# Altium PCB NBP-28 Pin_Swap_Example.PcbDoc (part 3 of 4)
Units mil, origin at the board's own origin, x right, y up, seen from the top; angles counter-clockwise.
Board outline 2716.54 x 4967.15 mil, 10 copper layers (Top Layer, Mid-Layer 1, VCC1V2, Mid-Layer 2, VCC, GND, MidLayer4, VCCINT, Mid-Layer 3, Bottom Layer), stack 81 mil thick; 254 components, 445 nets, 1667 pads, 770 vias.
Unrouted connection lines stored in the file: 611.
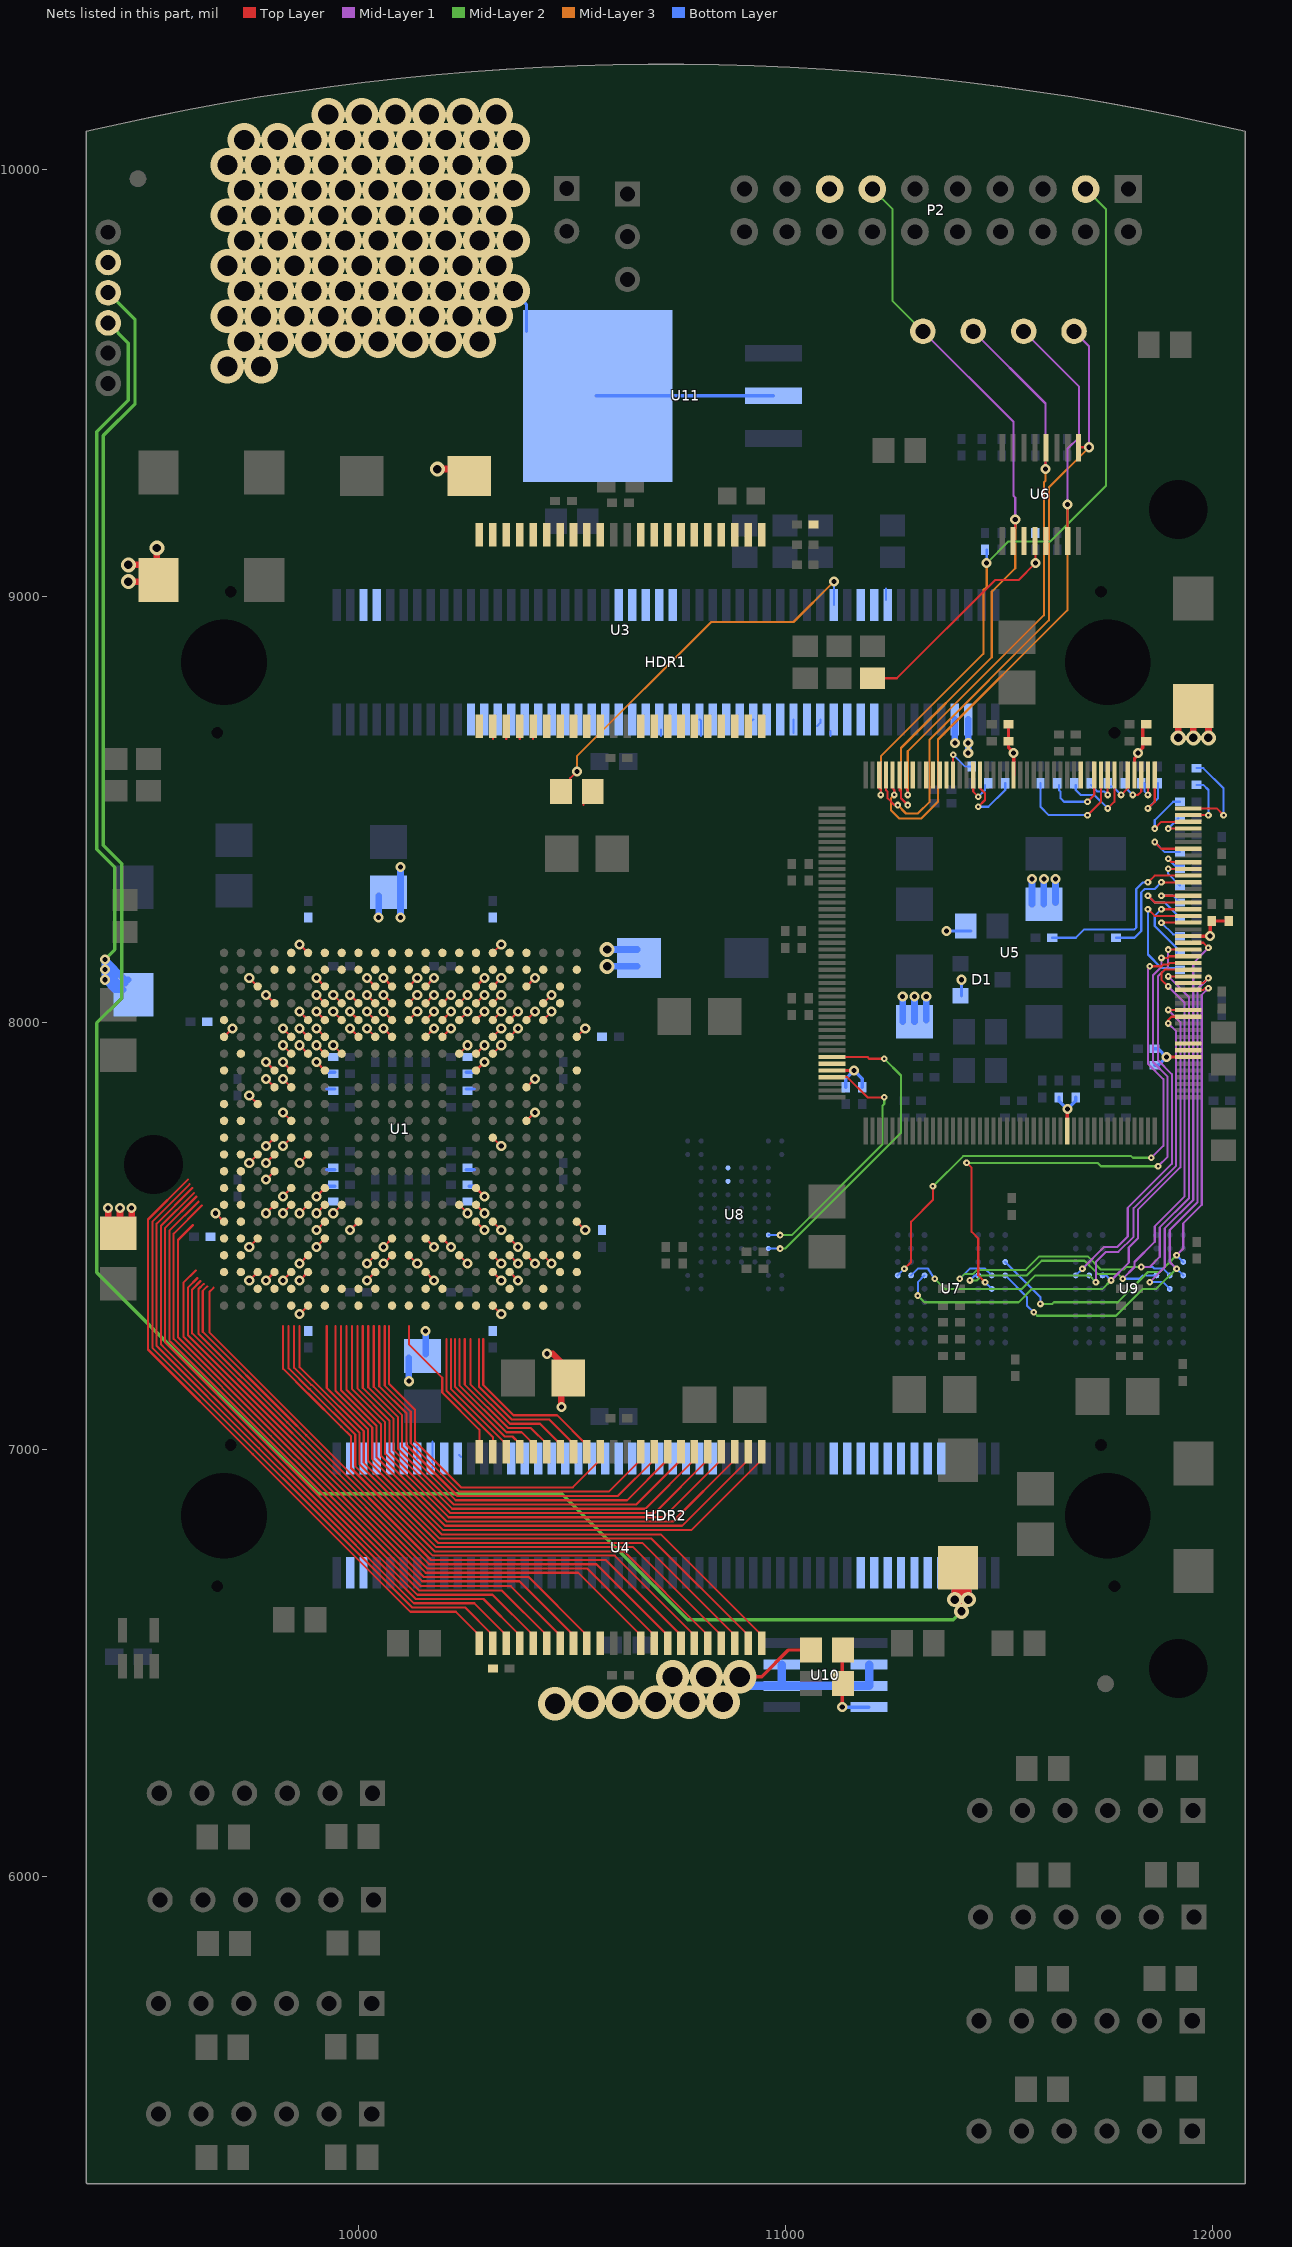
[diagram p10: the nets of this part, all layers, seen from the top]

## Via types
v1: diameter 23.62, hole 11.81, Top Layer to Bottom Layer, 495 vias
v2: diameter 78.74, hole 47.24, Top Layer to Bottom Layer, 101 vias
v3: diameter 15.75, hole 5.91, Top Layer to Bottom Layer, 92 vias
v4: diameter 35.43, hole 19.68, Top Layer to Bottom Layer, 59 vias
v5: diameter 19.68, hole 7.87, Top Layer to Bottom Layer, 23 vias

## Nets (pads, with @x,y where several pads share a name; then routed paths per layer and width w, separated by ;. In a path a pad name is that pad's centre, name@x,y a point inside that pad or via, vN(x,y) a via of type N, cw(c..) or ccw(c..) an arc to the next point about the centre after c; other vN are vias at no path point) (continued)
NetR26_1: R26.1 U5.126 | length 154.1
  Top Layer w5: v3(11865.62,8424.19) 11881.37,8408.44 U5.126@11944.36,8408.44
  Bottom Layer w5: v3(11865.62,8424.19) 11889.24,8400.57 R26.1@11924.67,8400.57
NetR27_1: R27.1 U5.124 | length 92.5
  Top Layer w5: v3(11897.11,8384.82) 11904.99,8376.95 U5.124@11944.36,8376.95
  Bottom Layer w5: v3(11897.11,8384.82) 11912.86,8369.07 R27.1@11932.55,8369.07
NetR28_1: R28.1 U5.123 | length 98
  Top Layer w5: v3(11897.11,8361.2) U5.123@11944.36,8361.2
  Bottom Layer w5: v3(11897.11,8361.2) 11897.11,8349.39 R28.1@11924.67,8321.83
NetR29_1: R29.1 U5.122 | length 432.3
  Top Layer w5: v3(11849.87,8329.7) 11865.62,8345.45 U5.122@11944.36,8345.45
  Bottom Layer w5: R29.1@11625.46,8199.78 11680.58,8199.78 11700.26,8219.47 11818.37,8219.47 11822.31,8223.41 11822.31,8313.96 11838.06,8329.7 v3(11849.87,8329.7)
NetR30_1: R30.1 U5.121 | length 276.1
  Top Layer w5: v3(11881.37,8329.7) U5.121@11944.36,8329.7
  Bottom Layer w5: R30.1@11775.07,8199.78 11818.37,8199.78 11834.12,8215.53 11834.12,8306.08 11842,8313.96 11865.62,8313.96 v3(11881.37,8329.7)
NetR31_1: R31.1 U5.119 | length 112.8
  Top Layer w5: v3(11881.37,8298.21) U5.119@11944.36,8298.21
  Bottom Layer w5: v3(11881.37,8298.21) 11908.93,8298.21 R31.1@11924.67,8282.46
NetR32_1: R32.1 U5.118 | length 197.7
  Top Layer w5: v3(11849.87,8298.21) 11865.62,8282.46 U5.118@11944.36,8282.46
  Bottom Layer w5: v3(11849.87,8298.21) 11865.62,8282.46 11889.24,8282.46 11916.8,8254.9 R32.1@11916.8,8243.09
NetR33_1: R33.1 U5.117 | length 193.1
  Top Layer w5: v3(11881.37,8266.71) U5.117@11944.36,8266.71
  Bottom Layer w5: v3(11881.37,8266.71) 11865.62,8250.96 11865.62,8227.34 11916.8,8176.16 R33.1@11916.8,8164.35
NetR34_1: R34.1 U5.116 | length 299.1
  Top Layer w5: v3(11849.87,8266.71) 11865.62,8250.96 U5.116@11944.36,8250.96
  Bottom Layer w5: v3(11849.87,8266.71) 11849.87,8160.41 11881.37,8128.92 R34.1@11928.61,8128.92
NetR35_1: R35.1 U5.115 | length 125.6
  Top Layer w5: v3(11881.37,8235.22) U5.115@11944.36,8235.22
  Bottom Layer w5: v3(11881.37,8235.22) 11908.93,8207.66 R35.1@11932.55,8207.66
NetR39_1: R39.1 U5.129 | length 80.6
  Top Layer w5: v3(11897.11,8455.69) U5.129@11944.36,8455.69
  Bottom Layer w5: v3(11897.11,8455.69) R39.1@11920.74,8479.31
NetR40_1: R40.1 U5.131 | length 138.8
  Top Layer w5: U5.131@11944.36,8487.18 v3(11991.6,8487.18)
  Bottom Layer w5: R40.1@11964.04,8558.05 11979.79,8558.05 11991.6,8546.24 v3(11991.6,8487.18)
NetR41_1: R41.1 U5.133 | length 154.1
  Top Layer w5: v3(11849.87,8502.93) 11865.62,8518.68 U5.133@11865.62,8581.67
  Bottom Layer w5: v3(11849.87,8502.93) 11873.49,8526.56 R41.1@11873.49,8561.99
NetR42_1: R42.1 U5.134 | length 78.1
  Top Layer w5: v3(11849.87,8534.43) U5.134@11849.87,8581.67
  Bottom Layer w5: R42.1@11842,8561.99 11842,8542.3 v3(11849.87,8534.43)
NetR43_1: R43.1 U5.135 | length 98.7
  Top Layer w5: v3(11814.44,8534.43) 11826.25,8534.43 11834.12,8542.3 U5.135@11834.12,8581.67
  Bottom Layer w5: R43.1@11802.63,8565.92 11802.63,8546.24 v3(11814.44,8534.43)
NetR45_1: R45.1 U5.137 | length 93.4
  Top Layer w5: v3(11786.88,8534.43) 11802.63,8550.18 U5.137@11802.63,8581.67
  Bottom Layer w5: R45.1@11755.38,8554.11 11767.19,8554.11 v3(11786.88,8534.43)
NetR48_1: R48.1 U5.130 | length 181.9
  Top Layer w5: v3(11865.62,8455.69) 11881.37,8471.44 U5.130@11944.36,8471.44
  Bottom Layer w5: v3(11865.62,8455.69) 11865.62,8475.37 11908.93,8518.68 R48.1@11924.67,8518.68
NetR49_1: R49.1 U5.132 | length 234.8
  Top Layer w5: U5.132@11944.36,8502.93 12011.29,8502.93 v3(12027.04,8487.18)
  Bottom Layer w5: R49.1@11964.04,8597.42 11979.79,8597.42 12027.04,8550.18 v3(12027.04,8487.18)
NetR50_1: R50.1 U5.139 | length 189.8
  Top Layer w5: v3(11755.38,8502.93) 11771.13,8518.68 U5.139@11771.13,8581.67
  Bottom Layer w5: R50.1@11680.58,8558.05 11680.58,8546.24 11692.39,8534.43 11723.89,8534.43 v3(11755.38,8502.93)
NetR51_1: R51.1 U5.140 | length 96.4
  Top Layer w5: v3(11755.38,8534.43) U5.140@11755.38,8581.67
  Bottom Layer w5: R51.1@11716.01,8558.05 11731.39,8542.68 11747.13,8542.68 v3(11755.38,8534.43)
NetR52_1: R52.1 U5.141 | length 281
  Top Layer w5: v3(11708.14,8487.18) 11739.63,8518.68 U5.141@11739.63,8581.67
  Bottom Layer w5: R52.1@11597.9,8561.99 11597.9,8506.87 11617.59,8487.18 v3(11708.14,8487.18)
NetR53_1: R53.1 U5.142 | length 168.9
  Top Layer w5: v3(11708.14,8518.68) 11723.89,8534.43 U5.142@11723.89,8581.67
  Bottom Layer w5: R53.1@11641.21,8558.05 11641.21,8546.24 11645.15,8542.3 11645.15,8526.55 11653.02,8518.68 v3(11708.14,8518.68)
NetR54_1: R54.1 U5.159 | length 181.3
  Top Layer w5: v3(11452.23,8506.87) 11467.98,8522.62 11467.98,8538.37 11456.17,8550.18 U5.159@11456.17,8581.67
  Bottom Layer w5: v3(11452.23,8506.87) 11475.85,8506.87 11515.22,8546.24 R54.1@11515.22,8561.99
NetR55_1: R55.1 U5.160 | length 90.2
  Top Layer w5: U5.160@11440.42,8581.67 11440.42,8542.3 v3(11452.23,8530.49)
  Bottom Layer w5: v3(11452.23,8530.49) 11467.98,8546.24 R55.1@11467.98,8558.05
NetR56_1: R56.1 U5.163 | length 102
  Top Layer w5: U5.163@11393.18,8581.67 v3(11393.18,8628.92)
  Bottom Layer w5: v3(11393.18,8628.92) 11420.74,8601.36 R56.1@11436.48,8601.36
NetR64_2: R64.2 R65.1 U10.4 | length 197.5
  Top Layer w7.87: v1(11133.33,6396.63) 11133.33,6528.52 R64.2@11135.3,6530.49
  Bottom Layer w7.87: v1(11133.33,6396.63) U10.4@11196.13,6396.63
NEXUS_TCK: HDR1.82 U1.A19
NEXUS_TDI: HDR1.84 U1.B19 | length 27.6
  Bottom Layer w5: HDR1.84@11235.7,8991.12 11235.7,9018.68
NEXUS_TDO: HDR1.76 R2.1 | length 896.6
  Top Layer w5: R2.1@10495.54,8561.99 10495.54,8573.8 v1(10511.29,8589.55)
  Mid-Layer 3 w5: v1(10511.29,8589.55) 10511.29,8624.98 10826.25,8939.94 11019.16,8939.94 v1(11113.65,9034.43)
  Bottom Layer w5: HDR1.76@11113.65,8979.31 v1(11113.65,9034.43)
NEXUS_TDO_R: R2.2 U1.D13 | length 43.6
  Top Layer w5: U1.D13@10156.96,8046.24 v1(10176.64,8065.93) ; 10527.04,8510.81 R2.2@10527.04,8526.55
NEXUS_TMS: HDR1.80 U1.D15 | length 27.8
  Top Layer w5: U1.D15@10235.7,8046.24 v1(10255.38,8065.93)
NFLASH_CS: U5.41 U8.H2 | length 609.3
  Top Layer w5: U5.41@11109.71,7873.01 11145.15,7873.01 11192.39,7825.77 v3(11231.76,7825.77)
  Mid-Layer 2 w5: v3(10987.67,7502.93) 11015.22,7502.93 11227.82,7715.53 11227.82,7806.08 11231.76,7810.02 v3(11231.76,7825.77)
  Bottom Layer w5: U8.H2@10960.11,7502.93 v3(10987.67,7502.93)
NOE: U1.H22 U5.38 U8.J2 | length 736.8
  Top Layer w5: U5.38@11109.71,7920.26 11192.39,7920.26 11196.33,7916.32 v3(11231.76,7916.32)
  Mid-Layer 2 w5: v3(10987.67,7471.44) 10999.48,7471.44 11271.13,7743.09 11271.13,7876.95 v3(11231.76,7916.32)
  Bottom Layer w5: U8.J2@10960.11,7471.44 v3(10987.67,7471.44)
NRESETOUT: U1.M17 U5.97 U8.D5 | length 27.8
  Top Layer w5: U1.M17@10314.44,7731.28 v1(10334.12,7711.59)
NSDRAM_CAS: U5.108 U7.F7 U9.F7 | length 1367
  Top Layer w5: v3(11897.11,8085.61) 11881.37,8101.36 11881.37,8117.11 11889.24,8124.98 U5.108@11944.36,8124.98
  Mid-Layer 1 w5: v3(11790.82,7400.57) 11818.37,7428.13 11818.37,7439.94 11865.62,7487.18 11865.62,7523.34 11935.85,7593.58 11935.85,8046.87 v3(11897.11,8085.61)
  Mid-Layer 2 w5: v3(11432.55,7396.63) 11448.3,7396.63 11460.11,7408.44 11566.41,7408.44 11600.89,7442.93 11701.21,7442.93 11732.08,7412.07 11779.32,7412.07 v3(11790.82,7400.57)
  Bottom Layer w5: v3(11432.55,7396.63) 11444.36,7408.44 U7.F7@11452.23,7408.44 ; v3(11790.82,7400.57) 11830.19,7400.57 11838.06,7408.44 U9.F7@11869.56,7408.44
NSDRAM_CS: U5.105 U7.G9 U9.G9 | length 1227
  Top Layer w5: U5.105@11944.36,8077.74 11979.79,8077.74 11983.73,8081.67 v3(11991.6,8081.67)
  Mid-Layer 1 w5: v3(11916.8,7455.69) 11932.55,7471.44 11932.55,7530.49 11975.85,7573.8 11975.85,8065.93 v3(11991.6,8081.67)
  Mid-Layer 2 w5: v3(11597.9,7341.52) 11625.46,7341.52 11629.4,7345.45 11779,7345.45 11849.87,7416.32 11877.43,7416.32 v3(11916.8,7455.69)
  Bottom Layer w5: U7.G9@11515.22,7439.94 11597.9,7357.26 v3(11597.9,7341.52) ; v3(11916.8,7455.69) U9.G9@11932.55,7439.94
NSDRAM_RAS: U5.107 U7.F8 U9.F8 | length 1434.7
  Top Layer w5: v3(11897.11,8109.23) U5.107@11944.36,8109.23
  Mid-Layer 1 w5: v3(11834.12,7428.13) 11853.81,7428.13 11877.43,7451.75 11877.43,7521.01 11945.85,7589.44 11945.85,8060.49 v3(11897.11,8109.23)
  Mid-Layer 2 w5: v3(11408.93,7400.57) 11420.42,7412.07 11440.11,7412.07 11449.48,7421.44 11563.65,7421.44 11595.15,7452.93 11708.87,7452.93 11739.74,7422.07 11792.63,7422.07 11798.69,7428.13 v3(11834.12,7428.13)
  Bottom Layer w5: v3(11408.93,7400.57) 11432.55,7424.19 11467.98,7424.19 U7.F8@11483.73,7408.44 ; v3(11834.12,7428.13) 11861.34,7428.13 11865.27,7424.19 11885.3,7424.19 U9.F8@11901.05,7408.44
NSDRAM_WE: U5.106 U7.F9 U9.F9 | length 1297.4
  Top Layer w5: U5.106@11944.36,8093.48 11979.79,8093.48 v3(11991.6,8105.3)
  Mid-Layer 1 w5: v3(11916.8,7424.19) 11901.05,7439.94 11901.05,7514.74 11965.85,7579.55 11965.85,8079.55 v3(11991.6,8105.3)
  Mid-Layer 2 w5: v3(11582.15,7321.83) 11590.03,7313.96 11775.07,7313.96 11838.06,7376.95 11869.56,7376.95 v3(11916.8,7424.19)
  Bottom Layer w5: U7.F9@11515.22,7408.44 11566.41,7357.26 11566.41,7337.58 v3(11582.15,7321.83) ; v3(11916.8,7424.19) U9.F9@11932.55,7408.44
NTRST: P2.3 R57.1 U5.174 | length 1796.4
  Top Layer w5: U5.174@11219.95,8581.67 11219.95,8550.18 11223.89,8546.24 v3(11223.89,8534.43)
  Mid-Layer 2 w5: v1(11471.92,9077.74) 11523.1,9128.92 11621.52,9128.92 11751.45,9258.84 11751.45,9906.87 P2.3@11703.81,9954.51
  Mid-Layer 3 w5: v3(11223.89,8534.43) 11223.89,8624.98 11464.04,8865.14 11464.04,9014.74 11471.92,9022.62 v1(11471.92,9077.74)
  Bottom Layer w5: v1(11471.92,9077.74) R57.1@11471.92,9109.23
NWAIT: U1.J19 U5.144 | length 27.8
  Top Layer w5: U1.J19@10393.18,7849.39 v1(10412.86,7869.08)
NWE: U1.L19 U5.39 U8.C5 | length 27.8
  Top Layer w5: U1.L19@10393.18,7770.65 v1(10412.86,7790.34)
PP_CTRL.NRESETIN: P2.15 R24.1 U1.B13 U5.96
PRO_P.SSPCLK: U1.E20 U5.165 | length 27.8
  Top Layer w5: U1.E20@10432.55,8006.87 v1(10452.23,8026.56)
PRO_P.SSPEN: U1.D21 U5.166
PRO_P.SSPFRM: U1.G17 U5.164 | length 27.8
  Top Layer w5: U1.G17@10314.44,7928.13 v1(10334.12,7947.82)
PRO_P.SSPRX_UART2RX: U1.D17 U5.169 | length 27.8
  Top Layer w5: U1.D17@10314.44,8046.24 v1(10334.12,8065.93)
PRO_P.SSPTX_UART2TX: U1.C21 U5.167
PROCESSOR_TDI: R1.2 U1.B22 U6.3 U6.5
PROCESSOR_TDO: R6.1 U6.4 | length 544.8
  Top Layer w5: R6.1@11204.2,8808.05 11261.29,8808.05 11491.6,9038.37 11546.72,9038.37 v1(11586.09,9077.74) U6.4@11586.09,9128.92
RAM0_DATA0: HDR2.42 U1.N6 | length 27.8
  Top Layer w5: v1(9861.68,7672.22) U1.N6@9881.37,7691.91
RAM0_DATA1: HDR2.40 U1.AA13
RAM0_DATA2: HDR2.38 U1.AB13
RAM0_DATA3: HDR2.36 U1.W11 | length 27.8
  Top Layer w5: v1(10058.53,7436) U1.W11@10078.22,7455.69
RAM0_DATA4: HDR2.34 U1.U9 | length 27.8
  Top Layer w5: v1(9979.79,7514.74) U1.U9@9999.48,7534.43
RAM0_DATA5: HDR2.32 U1.W10 | length 27.8
  Top Layer w5: v1(10019.16,7436) U1.W10@10038.85,7455.69
RAM0_DATA6: HDR2.30 U1.M4 | length 27.8
  Top Layer w5: v1(9782.94,7711.59) U1.M4@9802.63,7731.28
RAM0_DATA7: HDR2.28 U1.AA10
RAM0_OE: HDR1.41 U1.C12 | length 27.8
  Top Layer w5: U1.C12@10117.59,8085.61 v1(10137.27,8105.3)
RAM0_WE: HDR1.79 U1.E19 | length 27.8
  Top Layer w5: U1.E19@10393.18,8006.87 v1(10412.86,8026.56)
RAM1_DATA0: HDR1.45 U1.A14
RAM1_DATA1: HDR1.49 U1.E13 | length 43.6
  Top Layer w5: U1.E13@10156.96,8006.87 v1(10176.64,8026.56)
  Bottom Layer w5: 10708.14,8672.22 HDR1.49@10708.14,8687.97
RAM1_DATA2: HDR1.53 U1.F13 | length 27.8
  Top Layer w5: U1.F13@10156.96,7967.5 v1(10176.64,7987.19)
RAM1_DATA3: HDR1.57 U1.D12 | length 27.8
  Top Layer w5: U1.D12@10117.59,8046.24 v1(10137.27,8065.93)
RAM1_DATA4: HDR1.55 U1.E14 | length 68.8
  Top Layer w5: U1.E14@10196.33,8006.87 v1(10216.01,8026.56)
  Bottom Layer w5: HDR1.55@10798.69,8711.59 10802.63,8707.66 10802.63,8672.22
RAM1_DATA5: HDR1.51 U1.A15
RAM1_DATA6: HDR1.47 U1.C13 | length 27.8
  Top Layer w5: U1.C13@10156.96,8085.61 v1(10176.64,8105.3)
RAM1_DATA7: HDR1.43 U1.F11 | length 27.8
  Top Layer w5: v1(10058.53,7987.19) U1.F11@10078.22,7967.5
RAM1_OE: HDR1.39 U1.E11 | length 27.8
  Top Layer w5: v1(10058.53,8026.56) U1.E11@10078.22,8006.87
RAM1_WE: HDR1.61 U1.F14 | length 27.8
  Top Layer w5: U1.F14@10196.33,7967.5 v1(10216.01,7987.19)
RAM_ADDR0: HDR1.21 U1.H4 | length 27.8
  Top Layer w5: v1(9782.94,7908.45) U1.H4@9802.63,7888.76
RAM_ADDR1: HDR1.25 U1.G5 | length 27.8
  Top Layer w5: v1(9822.31,7947.82) U1.G5@9842,7928.13
RAM_ADDR2: HDR1.29 U1.B8
RAM_ADDR3: HDR1.33 U1.F7 | length 27.8
  Top Layer w5: v1(9901.05,7987.19) U1.F7@9920.74,7967.5
RAM_ADDR4: HDR1.65 U1.E16 | length 27.8
  Top Layer w5: U1.E16@10275.07,8006.87 v1(10294.75,8026.56)
RAM_ADDR5: HDR1.69 U1.E17 | length 59.3
  Top Layer w5: U1.E17@10314.44,8006.87 v1(10334.12,8026.56)
  Bottom Layer w5: HDR1.69@11019.16,8680.1 HDR1.69@11019.16,8711.59
RAM_ADDR6: HDR1.73 U1.E18 | length 46.8
  Top Layer w5: U1.E18@10353.81,8006.87 v1(10373.49,8026.56)
  Bottom Layer w5: HDR1.73@11074.28,8695.85 11082.15,8703.72 HDR1.73@11082.15,8711.59
RAM_ADDR7: HDR1.77 U1.F17 | length 27.8
  Top Layer w5: U1.F17@10314.44,7967.5 v1(10334.12,7987.19)
RAM_ADDR8: HDR1.75 U1.D20 | length 39.7
  Top Layer w5: U1.D20@10432.55,8046.24 v1(10452.23,8065.93)
  Bottom Layer w5: 11105.78,8672.22 HDR1.75@11105.78,8684.04
RAM_ADDR9: HDR1.71 U1.B20
RAM_ADDR10: HDR1.67 U1.C19 | length 27.8
  Top Layer w5: U1.C19@10393.18,8085.61 v1(10412.86,8105.3)
RAM_ADDR11: HDR1.63 U1.D16 | length 70.5
  Top Layer w5: U1.D16@10275.07,8046.24 v1(10294.75,8065.93)
  Bottom Layer w5: 10916.8,8672.22 10916.8,8703.72 HDR1.63@10924.67,8711.59
RAM_ADDR12: HDR1.59 U1.C16 | length 27.8
  Top Layer w5: U1.C16@10275.07,8085.61 v1(10294.75,8105.3)
RAM_ADDR13: HDR1.35 U1.D9 | length 27.8
  Top Layer w5: v1(9979.79,8065.93) U1.D9@9999.48,8046.24
RAM_ADDR14: HDR1.31 U1.H5 | length 27.8
  Top Layer w5: v1(9822.31,7908.45) U1.H5@9842,7888.76
RAM_ADDR15: HDR1.27 U1.J4 | length 27.8
  Top Layer w5: v1(9782.94,7869.08) U1.J4@9802.63,7849.39
RAM_ADDR16: HDR1.23 U1.K3 | length 27.8
  Top Layer w5: v1(9743.57,7829.71) U1.K3@9763.26,7810.02
RAM_CS: HDR1.37 U1.C10 | length 27.8
  Top Layer w5: v1(10019.16,8105.3) U1.C10@10038.85,8085.61
RED0: HDR1.6 U1.C3 | length 27.8
  Top Layer w5: v1(9743.57,8105.3) U1.C3@9763.26,8085.61
RED1: HDR1.8 U1.E1
REF_CLK: HDR2.4 U1.Y4 | length 27.8
  Top Layer w5: v1(9782.94,7396.63) U1.Y4@9802.63,7416.32
SCL: HDR2.5 U1.Y3 | length 27.8
  Top Layer w5: v1(9743.57,7396.63) U1.Y3@9763.26,7416.32
SDA: HDR2.3 U1.Y2
SDRAM_CKE: U5.102 U7.F3 U9.F3 | length 1319.2
  Top Layer w5: v3(11897.11,8030.49) U5.102@11944.36,8030.49
  Mid-Layer 1 w5: v3(11763.26,7396.63) 11804.94,7438.32 11804.94,7473.75 11826.25,7495.06 11826.25,7561.99 11925.85,7661.59 11925.85,8001.75 v3(11897.11,8030.49)
  Mid-Layer 2 w5: v3(11310.5,7361.2) 11326.25,7345.45 11546.72,7345.45 11578.22,7376.95 11743.57,7376.95 v3(11763.26,7396.63)
  Bottom Layer w5: v3(11310.5,7361.2) 11310.5,7392.7 U7.F3@11326.25,7408.44 ; U9.F3@11743.57,7408.44 11751.45,7408.44 v3(11763.26,7396.63)
SDRAM_CLK: U5.101 U7.F2 U9.F2 | length 1271.3
  Top Layer w5: v3(11897.11,7999) 11897.11,8006.87 11904.99,8014.74 U5.101@11944.36,8014.74
  Mid-Layer 1 w5: v3(11727.82,7392.7) 11727.82,7439.94 11751.45,7463.56 11780.61,7463.56 11816.25,7499.2 11816.25,7566.13 11915.85,7665.74 11915.85,7980.26 v3(11897.11,7999)
  Mid-Layer 2 w5: v3(11349.87,7400.57) 11373.49,7376.95 11554.59,7376.95 11586.09,7408.44 11712.08,7408.44 v3(11727.82,7392.7)
  Bottom Layer w5: U7.F2@11294.75,7408.44 11310.5,7424.19 11334.12,7424.19 v3(11349.87,7400.57) ; U9.F2@11712.08,7408.44 v3(11727.82,7392.7)
SDRAM_DQM0: U5.112 U9.E8 | length 946.4
  Top Layer w5: U5.112@11944.36,8187.97 11979.79,8187.97 v3(11991.6,8176.16)
  Mid-Layer 1 w5: v3(11853.81,7392.7) 11889.24,7428.13 11889.24,7518.68 11955.85,7585.3 11955.85,8140.41 v3(11991.6,8176.16)
  Bottom Layer w5: v3(11853.81,7392.7) 11885.3,7392.7 U9.E8@11901.05,7376.95
SDRAM_DQM1: U5.111 U9.F1 | length 945.5
  Top Layer w5: v3(11897.11,8172.22) U5.111@11944.36,8172.22
  Mid-Layer 1 w5: v3(11696.33,7424.19) 11747.51,7475.37 11778.28,7475.37 11802.63,7499.72 11802.63,7566.65 11905.85,7669.88 11905.85,7880.02 11873.49,7912.38 11873.49,8109.23 11897.11,8132.85 v3(11897.11,8172.22)
  Bottom Layer w5: U9.F1@11680.58,7408.44 v3(11696.33,7424.19)
SDRAM_DQM2: U5.110 U7.E8 | length 1356.2
  Top Layer w5: v3(11424.67,7672.22) 11436.48,7660.41 11436.48,7510.81 11452.23,7495.06 11452.23,7408.44 v3(11467.98,7392.7) ; v3(11881.37,8152.54) 11897.11,8152.54 11901.05,8156.48 U5.110@11944.36,8156.48
  Mid-Layer 1 w5: v3(11873.49,7664.35) 11895.85,7686.71 11895.85,7874.27 11861.68,7908.44 11861.68,8111.56 11881.37,8131.25 v3(11881.37,8152.54)
  Mid-Layer 2 w5: v3(11424.67,7672.22) 11731.76,7672.22 11739.63,7664.35 v3(11873.49,7664.35)
  Bottom Layer w5: v3(11467.98,7392.7) U7.E8@11483.73,7376.95
SDRAM_DQM3: U5.109 U7.F1 | length 1355.8
  Top Layer w5: v3(11279,7424.19) 11294.75,7439.94 11294.75,7534.43 11345.93,7585.61 v3(11345.93,7617.11) ; v3(11853.81,8132.85) 11881.37,8132.85 11885.3,8136.79 11897.11,8136.79 11901.05,8140.73 U5.109@11944.36,8140.73
  Mid-Layer 1 w5: v3(11853.81,8132.85) 11849.87,8124.98 11849.87,7904.51 11885.85,7868.52 11885.85,7712.15 v3(11857.74,7684.04)
  Mid-Layer 2 w5: v3(11345.93,7617.11) 11416.8,7687.97 11810.5,7687.97 11814.44,7684.04 v3(11857.74,7684.04)
  Bottom Layer w5: U7.F1@11263.26,7408.44 v3(11279,7424.19)
SP0: HDR2.79 U1.AA18
SP1: HDR2.81 U1.Y17 | length 27.8
  Top Layer w5: U1.Y17@10314.44,7416.32 v1(10334.12,7396.63)
SP2: HDR2.83 U1.AB20
SP3: HDR2.85 U1.W17 | length 27.8
  Top Layer w5: U1.W17@10314.44,7455.69 v1(10334.12,7436)
SP4: HDR2.87 U1.Y18 | length 27.8
  Top Layer w5: U1.Y18@10353.81,7416.32 v1(10373.49,7396.63)
SP5: HDR2.89 U1.AA20
SP6: HDR2.91 U1.W18 | length 27.8
  Top Layer w5: U1.W18@10353.81,7455.69 v1(10373.49,7436)
SP7: HDR2.90 U1.W21
SP8: HDR2.92 U1.W22
SP9: HDR2.88 U1.Y22
SP10: HDR2.86 U1.U17 | length 27.8
  Top Layer w5: U1.U17@10314.44,7534.43 v1(10334.12,7514.74)
SP11: HDR2.84 U1.W20 | length 27.8
  Top Layer w5: U1.W20@10432.55,7455.69 v1(10452.23,7436)
SP12: HDR2.82 U1.V18 | length 27.8
  Top Layer w5: U1.V18@10353.81,7495.06 v1(10373.49,7475.37)
SP13: HDR2.80 U1.Y21
SP14: HDR2.78 U1.U16 | length 27.8
  Top Layer w5: U1.U16@10275.07,7534.43 v1(10294.75,7514.74)
SP15: HDR2.76 U1.W19 | length 27.8
  Top Layer w5: U1.W19@10393.18,7455.69 v1(10412.86,7436)
SPI_CLK: HDR1.46 U1.G6 | length 27.8
  Top Layer w5: v1(9861.68,7947.82) U1.G6@9881.37,7928.13
SPI_DIN: HDR1.44 U1.E7 | length 27.8
  Top Layer w5: v1(9901.05,8026.56) U1.E7@9920.74,8006.87
SPI_DOUT: HDR1.50 U1.B11
SPI_MODE: HDR1.52 U1.D10 | length 27.8
  Top Layer w5: v1(10019.16,8065.93) U1.D10@10038.85,8046.24
SPI_SEL: HDR1.48 U1.E8 | length 27.8
  Top Layer w5: v1(9940.42,8026.56) U1.E8@9960.11,8006.87
SRAM0_A0: U1.B7 U3.1 | length 4.9
  Top Layer w5: U3.1@10282.94,8695.85 U3.1@10282.94,8700.77
SRAM0_A1: U1.A8 U3.2 | length 34.4
  Top Layer w5: 10314.44,8666.32 U3.2@10314.44,8700.77
SRAM0_A2: U1.F6 U3.3 | length 62.3
  Top Layer w5: v1(9861.68,7987.19) U1.F6@9881.37,7967.5 ; 10345.93,8666.32 U3.3@10345.93,8700.77
SRAM0_A3: U1.J5 U3.4 | length 62.3
  Top Layer w5: v1(9822.31,7869.08) U1.J5@9842,7849.39 ; 10377.43,8666.32 U3.4@10377.43,8700.77
SRAM0_A4: U1.B9 U3.5 | length 34.4
  Top Layer w5: 10408.93,8666.32 U3.5@10408.93,8700.77
SRAM0_A5: U1.A18 U3.18
SRAM0_A6: U1.C17 U3.19 | length 27.8
  Top Layer w5: U1.C17@10314.44,8085.61 v1(10334.12,8105.3)
SRAM0_A7: U1.B18 U3.20
SRAM0_A8: U1.B17 U3.21
SRAM0_A9: U1.E15 U3.22 | length 27.8
  Top Layer w5: U1.E15@10235.7,8006.87 v1(10255.38,8026.56)
SRAM0_A10: U1.A13 U3.23
SRAM0_A11: U1.B12 U3.24
SRAM0_A12: U1.D11 U3.25 | length 27.8
  Top Layer w5: v1(10058.53,8065.93) U1.D11@10078.22,8046.24
SRAM0_A13: U1.A12 U3.26
SRAM0_A14: U1.C11 U3.27 | length 27.8
  Top Layer w5: v1(10058.53,8105.3) U1.C11@10078.22,8085.61
SRAM0_A15: U1.D4 U3.42 | length 27.8
  Top Layer w5: v1(9782.94,8065.93) U1.D4@9802.63,8046.24
SRAM0_A16: U1.B4 U3.43 | length 18.7
  Top Layer w5: U3.43@10314.44,9121.04 U3.43@10314.44,9139.74
SRAM0_A17: U1.H1 U3.44
SRAM0_A18: U1.B10 U3.28
SRAM0_D0: U1.E9 U3.7 | length 27.8
  Top Layer w5: v1(9979.79,8026.56) U1.E9@9999.48,8006.87
SRAM0_D1: U1.F9 U3.8 | length 27.8
  Top Layer w5: v1(9979.79,7987.19) U1.F9@9999.48,7967.5
SRAM0_D2: U1.E10 U3.9 | length 27.8
  Top Layer w5: v1(10019.16,8026.56) U1.E10@10038.85,8006.87
SRAM0_D3: U1.F10 U3.10 | length 27.8
  Top Layer w5: v1(10019.16,7987.19) U1.F10@10038.85,7967.5
SRAM0_D4: U1.E12 U3.13 | length 27.8
  Top Layer w5: U1.E12@10117.59,8006.87 v1(10137.27,8026.56)
SRAM0_D5: U1.B15 U3.14
SRAM0_D6: U1.A16 U3.15
SRAM0_D7: U1.D14 U3.16 | length 27.8
  Top Layer w5: U1.D14@10196.33,8046.24 v1(10216.01,8065.93)
SRAM0_D8: U1.A11 U3.29
SRAM0_D9: U1.A9 U3.30
SRAM0_D10: U1.D8 U3.31 | length 27.8
  Top Layer w5: v1(9940.42,8065.93) U1.D8@9960.11,8046.24
SRAM0_D11: U1.D7 U3.32 | length 27.8
  Top Layer w5: v1(9901.05,8065.93) U1.D7@9920.74,8046.24
SRAM0_D12: U1.E6 U3.35 | length 27.8
  Top Layer w5: v1(9861.68,8026.56) U1.E6@9881.37,8006.87
SRAM0_D13: U1.C7 U3.36 | length 27.8
  Top Layer w5: v1(9901.05,8105.3) U1.C7@9920.74,8085.61
SRAM0_D14: U1.F5 U3.37 | length 27.8
  Top Layer w5: v1(9822.31,7987.19) U1.F5@9842,7967.5
SRAM0_D15: U1.A7 U3.38
SRAM0_E: U1.A10 U3.6
SRAM0_LB: U1.B5 U3.39
SRAM0_OE: U1.A5 U3.41
SRAM0_UB: U1.G2 U3.40
SRAM0_W: U1.B16 U3.17
SRAM1_A0: U1.K1 U4.1 | length 1509.4
  Top Layer w5: 9599.71,7632.85 9506.41,7539.55 9506.41,7234.76 9751.85,6989.32 9840.01,6901.15 10121.16,6620 10227.88,6620 10282.94,6564.94 U4.1@10282.94,6546.24
SRAM1_A1: R19.2 U1.L1 U4.2 | length 1515.3
  Top Layer w5: 9603.88,7622.06 9516.41,7534.58 9516.41,7238.9 10125.31,6630 10249.38,6630 10314.44,6564.94 U4.2@10314.44,6546.24
SRAM1_A2: U1.M1 U4.3 | length 1523.9
  Top Layer w5: 9610,7613.17 9526.41,7529.57 9526.41,7243.04 9765.99,7003.46 9860.01,6909.44 10129.45,6640 10270.87,6640 10345.93,6564.94 U4.3@10345.93,6546.24
SRAM1_A3: U1.N1 U4.4 | length 1528.5
  Top Layer w5: 9613.65,7601.36 9536.41,7524.11 9536.41,7247.18 9539.45,7244.14 9540,7243.59 9775.99,7007.6 10133.59,6650 10292.37,6650 10377.43,6564.94 U4.4@10377.43,6546.24
SRAM1_A4: U1.P1 U4.5 | length 1538.2
  Top Layer w5: 9620,7593.48 9546.41,7519.89 9546.41,7251.33 9549.45,7248.28 9550,7247.73 9780.13,7017.6 9880.01,6917.72 10137.63,6660.1 10313.77,6660.1 10408.93,6564.94 U4.5@10408.93,6546.24
SRAM1_A5: U1.AA3 U4.18 | length 1416.6
  Top Layer w5: 9823.06,7290 9823.06,7189.42 9880.71,7131.77 9881.23,7131.77 9959.25,7053.75 9959.44,7053.75 9981.93,7031.27 9981.93,6957.22 10177.61,6761.54 10621.77,6761.54 10818.37,6564.94 U4.18@10818.37,6546.24
SRAM1_A6: U1.V3 U4.19 | length 1462.4
  Top Layer w5: v1(9743.57,7475.37) U1.V3@9763.26,7495.06 ; 9835.93,7290 9835.93,7190.69 9884.85,7141.77 9885.57,7141.77 9991.93,7035.41 9991.93,6961.37 10181.75,6771.54 10643.27,6771.54 10849.87,6564.94 U4.19@10849.87,6546.24
SRAM1_A7: U1.AA4 U4.20 | length 1452.4
  Top Layer w5: 9848.81,7290 9848.81,7191.96 9889,7151.77 9889.71,7151.77 10001.93,7039.55 10001.93,6965.51 10185.89,6781.54 10664.76,6781.54 10881.37,6564.94 U4.20@10881.37,6546.24
SRAM1_A8: U1.U2 U4.21 | length 1470.3
  Top Layer w5: 9861.68,7290 9861.68,7193.23 9893.14,7161.77 9893.85,7161.77 10011.93,7043.69 10011.93,6969.65 10190.04,6791.54 10686.26,6791.54 10912.86,6564.94 U4.21@10912.86,6546.24
SRAM1_A9: U1.Y6 U4.22 | length 1494.6
  Top Layer w5: v1(9861.68,7396.63) U1.Y6@9881.37,7416.32 ; 9925.31,7290 9925.31,7144.46 10021.93,7047.83 10021.93,6973.79 10194.18,6801.54 10707.75,6801.54 10944.36,6564.94 U4.22@10944.36,6546.24
SRAM1_A10: U1.AB7 U4.23 | length 1416.3
  Top Layer w5: 9945.33,7290 9945.33,7138.58 10031.93,7051.98 10031.93,6977.93 10198.32,6811.54 10779.54,6811.54 10944.36,6976.36 U4.23@10944.36,6995.06
SRAM1_A11: U1.W6 U4.24 | length 1390.7
  Top Layer w5: v1(9861.68,7436) U1.W6@9881.37,7455.69 ; 9958.2,7290 9958.2,7139.85 10041.93,7056.12 10041.93,6982.08 10202.46,6821.54 10758.05,6821.54 10912.86,6976.36 U4.24@10912.86,6995.06
SRAM1_A12: U1.N3 U4.25 | length 1337.3
  Top Layer w5: v1(9743.57,7672.22) U1.N3@9763.26,7691.91 ; 9971.08,7290 9971.08,7141.11 10051.93,7060.26 10051.93,6986.22 10206.6,6831.54 10736.55,6831.54 10881.37,6976.36 U4.25@10881.37,6995.06
SRAM1_A13: U1.P4 U4.26 | length 1283.9
  Top Layer w5: v1(9782.94,7632.85) U1.P4@9802.63,7652.54 ; 9983.95,7290 9983.95,7142.38 10061.93,7064.4 10061.93,6990.36 10210.75,6841.54 10715.06,6841.54 10849.87,6976.36 U4.26@10849.87,6995.06
SRAM1_A14: U1.R5 U4.27 | length 1230.5
  Top Layer w5: v1(9822.31,7593.48) U1.R5@9842,7613.17 ; 9996.82,7290 9996.82,7143.65 10071.93,7068.54 10071.93,6994.5 10214.89,6851.54 10693.56,6851.54 10818.37,6976.36 U4.27@10818.37,6995.06
SRAM1_A15: U1.AB12 U4.42 | length 317.6
  Top Layer w5: 10215.95,7258.84 10215.95,7142.8 10345.93,7012.82 U4.42@10345.93,6995.06
SRAM1_A16: U1.Y10 U4.43 | length 336.6
  Top Layer w5: v1(10019.16,7396.63) U1.Y10@10038.85,7416.32 ; 10205.95,7258.84 10205.95,7138.1 10314.44,7029.62 U4.43@10314.44,6995.06
SRAM1_A17: U1.AB11 U4.44 | length 363.4
  Top Layer w5: 10117.59,7290 10117.59,7246.78 10195.95,7168.41 10195.95,7133.96 10282.94,7046.97 U4.44@10282.94,6995.06
SRAM1_A18: U1.L2 U4.28 | length 1149.3
  Top Layer w5: 10009.7,7290 10009.7,7144.92 10081.93,7072.69 10081.93,6998.65 10219.03,6861.54 10672.06,6861.54 10786.88,6976.36 U4.28@10786.88,6995.06
SRAM1_D0: U1.R1 U4.7 | length 1552
  Top Layer w5: 9632.35,7572.35 9566.41,7506.41 9566.41,7259.61 9794.27,7031.74 9900.01,6926 10145.92,6680.1 10356.76,6680.1 10471.92,6564.94 U4.7@10471.92,6546.24
SRAM1_D1: U1.T1 U4.8 | length 1512.6
  Top Layer w5: 9611.57,7526.63 9576.41,7491.46 9576.41,7263.75 10148.61,6691.54 10376.81,6691.54 10503.41,6564.94 U4.8@10503.41,6546.24
SRAM1_D2: U1.T2 U4.9 | length 1421.3
  Top Layer w5: 9618.21,7420 9589.22,7391.02 9589.22,7265.08 9808.42,7045.88 9920.01,6934.29 10152.76,6701.54 10398.31,6701.54 10534.91,6564.94 U4.9@10534.91,6546.24
SRAM1_D3: U1.V7 U4.10 | length 27.8
  Top Layer w5: v1(9901.05,7475.37) U1.V7@9920.74,7495.06
SRAM1_D4: U1.V2 U4.13 | length 1514.4
  Top Layer w5: 9622.35,7402.35 9599.71,7379.71 9599.71,7268.73 9600,7268.44 10156.9,6711.54 10514.29,6711.54 10660.89,6564.94 U4.13@10660.89,6546.24
SRAM1_D5: U1.V1 U4.14 | length 1525.2
  Top Layer w5: 9629.42,7395.28 9609.71,7375.57 9609.71,7272.87 9822.56,7060.03 9868.83,7013.75 10161.04,6721.54 10535.79,6721.54 10692.39,6564.94 U4.14@10692.39,6546.24
SRAM1_D6: U1.W1 U4.15 | length 1532.6
  Top Layer w5: 9637,7388.71 9624.7,7376.41 9624.7,7272.03 9832.56,7064.17 10165.18,6731.54 10557.28,6731.54 10723.89,6564.94 U4.15@10723.89,6546.24
SRAM1_D7: U1.Y1 U4.16 | length 1544.9
  Top Layer w5: 9645.15,7382.73 9634.7,7372.27 9634.7,7276.17 9836.7,7074.17 9877.12,7033.75 10169.32,6741.54 10578.78,6741.54 10755.38,6564.94 U4.16@10755.38,6546.24
SRAM1_D8: U1.AB9 U4.29 | length 1095.9
  Top Layer w5: 10022.57,7290 10022.57,7146.19 10091.93,7076.83 10091.93,7002.79 10223.17,6871.54 10650.57,6871.54 10755.38,6976.36 U4.29@10755.38,6995.06
SRAM1_D9: U1.N4 U4.30 | length 1070.3
  Top Layer w5: v1(9782.94,7672.22) U1.N4@9802.63,7691.91 ; 10035.45,7290 10035.45,7147.45 10101.93,7080.97 10101.93,7006.93 10227.31,6881.54 10629.07,6881.54 10723.89,6976.36 U4.30@10723.89,6995.06
SRAM1_D10: U1.T6 U4.31 | length 1016.9
  Top Layer w5: v1(9861.68,7554.11) U1.T6@9881.37,7573.8 ; 10048.32,7290 10048.32,7148.72 10111.93,7085.11 10111.93,7011.07 10231.46,6891.54 10607.58,6891.54 10692.39,6976.36 U4.31@10692.39,6995.06
SRAM1_D11: U1.AA9 U4.32 | length 935.7
  Top Layer w5: 10061.15,7290 10061.15,7150.04 10121.93,7089.26 10121.93,7015.21 10235.6,6901.54 10586.08,6901.54 10660.89,6976.36 U4.32@10660.89,6995.06
SRAM1_D12: U1.U7 U4.35 | length 848.3
  Top Layer w5: v1(9901.05,7514.74) U1.U7@9920.74,7534.43 ; 10071.15,7290 10071.15,7154.18 10131.93,7093.4 10131.93,7019.36 10239.74,6911.54 10501.59,6911.54 10566.41,6976.36 U4.35@10566.41,6995.06
SRAM1_D13: U1.AB15 U4.36 | length 424.4
  Top Layer w5: 10291.88,7258.84 10291.88,7151.72 10362.91,7080.69 10465.24,7080.69 10534.91,7011.02 U4.36@10534.91,6995.06
SRAM1_D14: U1.AA14 U4.37 | length 406.9
  Top Layer w5: 10281.88,7258.84 10281.88,7147.58 10358.77,7070.69 10446.48,7070.69 10503.41,7013.76 U4.37@10503.41,6995.06
SRAM1_D15: U1.W12 U4.38 | length 419.9
  Top Layer w5: U1.W12@10117.59,7455.69 v1(10137.27,7436) ; 10261.76,7258.84 10261.76,7153.56 10354.63,7060.69 10424.99,7060.69 10471.92,7013.76 U4.38@10471.92,6995.06
SRAM1_E: U1.P2 U4.6 | length 1543.4
  Top Layer w5: 9625,7581.67 9556.41,7513.08 9556.41,7255.47 9559.45,7252.43 10141.78,6670.1 10335.26,6670.1 10440.42,6564.94 U4.6@10440.42,6546.24
SRAM1_LB: U1.V11 U4.39 | length 402.1
  Top Layer w5: v1(10058.53,7475.37) U1.V11@10078.22,7495.06 ; 10248.7,7258.84 10248.7,7152.47 10350.49,7050.69 10403.49,7050.69 10440.42,7013.76 U4.39@10440.42,6995.06
SRAM1_OE: U1.N2 U4.41 | length 337.2
  Top Layer w5: 10225.95,7258.84 10225.95,7146.94 10342.2,7030.69 10360.5,7030.69 10377.43,7013.76 U4.41@10377.43,6995.06
SRAM1_UB: U1.M5 U4.40 | length 384.2
  Top Layer w5: v1(9822.31,7711.59) U1.M5@9842,7731.28 ; 10235.95,7258.84 10235.95,7151.08 10346.35,7040.69 10382,7040.69 10408.93,7013.76 U4.40@10408.93,6995.06
SRAM1_W: U1.W2 U4.17 | length 1558.5
  Top Layer w5: 9660,7379.71 9650,7369.71 9650,7275.01 10173.47,6751.54 10600.27,6751.54 10786.88,6564.94 U4.17@10786.88,6546.24
SW0: HDR2.44 U1.Y13 | length 27.8
  Top Layer w5: U1.Y13@10156.96,7416.32 v1(10176.64,7396.63)
SW1: HDR2.46 U1.AB16
SW2: HDR2.48 U1.L5 | length 27.8
  Top Layer w5: v1(9822.31,7790.34) U1.L5@9842,7770.65
SW3: HDR2.50 U1.W15 | length 27.8
  Top Layer w5: U1.W15@10235.7,7455.69 v1(10255.38,7436)
SW4: HDR2.52 U1.V13 | length 27.8
  Top Layer w5: U1.V13@10156.96,7495.06 v1(10176.64,7475.37)
SW5: HDR2.54 U1.AB18
SW6: HDR2.56 U1.V14 | length 27.8
  Top Layer w5: U1.V14@10196.33,7495.06 v1(10216.01,7475.37)
SW7: HDR2.58 U1.AB19
SWC0: HDR2.18 U1.AA7
SWC1: HDR2.16 U1.T5 | length 90.8
  Top Layer w5: v1(9822.31,7554.11) U1.T5@9842,7573.8
  Bottom Layer w5: HDR2.16@10172.7,6955.69 10172.7,7018.68
SWC2: HDR2.14 U1.T4 | length 55.4
  Top Layer w5: v1(9782.94,7554.11) U1.T4@9802.63,7573.8
  Bottom Layer w5: HDR2.14@10137.27,6979.31 HDR2.14@10137.27,7006.87
SWC3: HDR2.6 U1.AB5
SWR0: HDR2.20 U1.AA8 | length 5.6
  Bottom Layer w5: HDR2.20@10235.7,6987.18 HDR2.20@10239.63,6983.25
SWR1: HDR2.12 U1.R2
SWR2: HDR2.10 U1.AA5
SWR3: HDR2.8 U1.Y5 | length 27.8
  Top Layer w5: v1(9822.31,7396.63) U1.Y5@9842,7416.32
TCLK: TP4.1 U5.173 U6.9 | length 1476.8
  Top Layer w5: U5.173@11235.7,8581.67 11235.7,8546.24 11239.63,8542.3 11239.63,8526.55 11255.38,8510.81 v3(11263.26,8510.81) ; U6.9@11688.45,9349.39 v1(11712.08,9349.39)
  Mid-Layer 1 w5: TP4.1@11676.64,9621.04 11712.08,9585.61 v1(11712.08,9349.39)
  Mid-Layer 3 w5: v3(11263.26,8510.81) 11282.94,8491.12 11310.5,8491.12 11338.06,8518.68 11338.06,8664.35 11617.59,8943.88 11617.59,9254.9 v1(11712.08,9349.39)
TDI: TP6.1 U5.172 U6.7 | length 1600.1
  Top Layer w5: U5.172@11251.45,8581.67 11251.45,8550.18 11255.38,8546.24 v3(11255.38,8534.43) ; U6.7@11660.89,9130.89 v1(11660.89,9215.53)
  Mid-Layer 1 w5: TP6.1@11558.53,9621.04 11688.45,9491.12 11688.45,9373.01 11660.89,9345.45 v1(11660.89,9215.53)
  Mid-Layer 3 w5: v3(11255.38,8534.43) 11247.51,8526.55 11247.51,8499 11267.19,8479.31 11318.37,8479.31 11357.74,8518.68 11357.74,8664.35 11660.89,8967.5 v1(11660.89,9215.53)
TDO: P2.13 TP3.1 U5.171 U6.2 | length 1809.7
  Top Layer w5: U5.171@11267.19,8581.67 11267.19,8546.24 11271.13,8542.3 11271.13,8526.56 v3(11286.88,8510.81) ; U6.2@11530.97,9152.54 11538.85,9160.41 v1(11538.85,9180.1)
  Mid-Layer 1 w5: TP3.1@11322.31,9621.04 11534.91,9408.44 11534.91,9235.22 11538.85,9231.28 v1(11538.85,9180.1)
  Mid-Layer 2 w5: P2.13@11203.81,9954.51 11251.45,9906.87 11251.45,9691.91 TP3.1@11322.31,9621.04
  Mid-Layer 3 w5: v3(11286.88,8510.81) 11271.13,8526.56 11271.13,8644.67 11483.73,8857.26 11483.73,9010.81 11538.85,9065.92 v1(11538.85,9180.1)
TEST: HDR1.81 U1.F18 | length 27.8
  Top Layer w5: U1.F18@10353.81,7967.5 v1(10373.49,7987.19)
TMS: TP5.1 U5.170 U6.12 | length 1388.5
  Top Layer w5: U5.170@11282.94,8581.67 11282.94,8550.18 11286.88,8546.24 v3(11286.88,8534.43) ; v1(11609.71,9298.21) U6.12@11609.71,9347.42
  Mid-Layer 1 w5: TP5.1@11440.42,9621.04 11609.71,9451.75 v1(11609.71,9298.21)
  Mid-Layer 3 w5: v3(11286.88,8534.43) 11286.88,8636.79 11605.78,8955.69 11605.78,9266.71 11609.71,9270.65 v1(11609.71,9298.21)
VCC1V2: C16.1 C17.1 C18.1 C19.1 C20.1 C21.1 C22.1 C23.1 C24.1 C25.1 C26.1 C27.1 C28.1 C29.1 C130.1 C131.1 TP9.1 U1.G7 U1.G8 U1.G15 U1.G16 U1.H7 U1.H16 U1.R7 U1.R16 U1.T7 U1.T8 U1.T15 U1.T16 U11.2 U11.4 | length 1550.3
  Top Layer w5: v1(9901.05,7554.11) U1.T7@9920.74,7573.8 ; v1(9901.05,7593.48) U1.R7@9920.74,7613.17 ; v1(9901.05,7908.45) U1.H7@9920.74,7888.76 ; v1(9901.05,7947.82) U1.G7@9920.74,7928.13 ; v1(9940.42,7554.11) U1.T8@9960.11,7573.8 ; v1(9940.42,7947.82) U1.G8@9960.11,7928.13 ; U1.T15@10235.7,7573.8 v1(10255.38,7554.11) ; U1.G15@10235.7,7928.13 v1(10255.38,7947.82) ; U1.T16@10275.07,7573.8 v1(10294.75,7554.11) ; U1.R16@10275.07,7613.17 v1(10294.75,7593.48) ; U1.H16@10275.07,7888.76 v1(10294.75,7908.45) ; U1.G16@10275.07,7928.13 v1(10294.75,7947.82)
  Top Layer w15.75: v4(9460.11,9034.43) C130.1@9534.91,9034.43 ; v4(9460.11,9073.8) C130.1@9523.1,9073.8 ; C130.1@9527.04,9046.24 v4(9527.04,9113.17) ; v4(10184.52,9298.21) C131.1@10243.57,9298.21
  Bottom Layer w7.87: 9924.67,7617.11 C20.1@9944.36,7617.11 ; 9924.67,7656.48 C25.1@9944.36,7656.48 ; 9924.67,7845.45 C23.1@9944.36,7845.45 ; 9924.67,7884.82 C21.1@9944.36,7884.82 ; C27.1@10251.45,7656.48 10271.13,7656.48 ; C29.1@10251.45,7845.45 10271.13,7845.45 ; C19.1@10251.45,7884.82 10271.13,7884.82 ; C18.1@10259.32,7617.11 10271.13,7617.11 ; v2(10361.68,9715.53) 10393.18,9684.04 U11.4@10393.18,9621.04 ; U11.4@10556.17,9469.86 U11.4@10560.5,9469.86 U11.2@10971.92,9469.86
  Bottom Layer w15.75: v1(10046.72,8247.03) C17.1@10046.72,8298.21 ; v1(10097.9,8247.03) v1(10097.9,8365.14) ; v1(10117.59,7160.41) C16.1@10117.59,7215.53 ; C16.1@10156.96,7223.41 v1(10156.96,7278.52)
  other v2: 9692.39,9538.37 9771.13,9538.37 9731.76,9597.42 9810.5,9597.42 9889.24,9597.42 9967.98,9597.42 10046.72,9597.42 10125.46,9597.42 10204.2,9597.42 10282.94,9597.42 9692.39,9656.48 9771.13,9656.48 9849.87,9656.48 9928.61,9656.48 10007.35,9656.48 10086.09,9656.48 10164.83,9656.48 10243.57,9656.48 10322.31,9656.48 9731.76,9715.53 9810.5,9715.53 9889.24,9715.53 9967.98,9715.53 10046.72,9715.53 10125.46,9715.53 10204.2,9715.53 10282.94,9715.53 9692.39,9774.59 9771.13,9774.59 9849.87,9774.59 9928.61,9774.59 10007.35,9774.59 10086.09,9774.59 10164.83,9774.59 10243.57,9774.59 10322.31,9774.59 9731.76,9833.64 9810.5,9833.64 9889.24,9833.64 9967.98,9833.64 10046.72,9833.64 10125.46,9833.64 10204.2,9833.64 10282.94,9833.64 10361.68,9833.64 9692.39,9892.7 9771.13,9892.7 9849.87,9892.7 9928.61,9892.7 10007.35,9892.7 10086.09,9892.7 10164.83,9892.7 10243.57,9892.7 10322.31,9892.7 9731.76,9951.75 9810.5,9951.75 9889.24,9951.75 9967.98,9951.75 10046.72,9951.75 10125.46,9951.75 10204.2,9951.75 10282.94,9951.75 10361.68,9951.75 9692.39,10010.81 9771.13,10010.81 9849.87,10010.81 9928.61,10010.81 10007.35,10010.81 10086.09,10010.81 10164.83,10010.81 10243.57,10010.81 10322.31,10010.81 9731.76,10069.86 9810.5,10069.86 9889.24,10069.86 9967.98,10069.86 10046.72,10069.86 10125.46,10069.86 10204.2,10069.86 10282.94,10069.86 10361.68,10069.86 9928.61,10128.92 10007.35,10128.92 10086.09,10128.92 10164.83,10128.92 10243.57,10128.92 10322.31,10128.92
VCC1V8: C88.1 C89.1 C90.1 C91.1 C92.1 C93.1 C94.1 C95.1 C96.1 C97.1 C98.1 C99.1 C100.1 C101.1 C132.1 C133.1 D1.1 HDR1.93 HDR1.95 HDR2.93 HDR2.95 R59.1 TP2.1 U5.40 U5.75 U5.95 U5.113 U5.136 U5.154 | length 6648
  Top Layer w7.87: U5.40@11109.71,7888.76 v1(11160.89,7888.76) ; C95.1@11523.1,8699.78 C96.1@11523.1,8660.41 11523.1,8644.67 v1(11534.91,8632.85) U5.154@11534.91,8581.67 ; U5.75@11660.89,7747.03 v1(11660.89,7798.21) ; U5.136@11818.37,8581.67 11818.37,8621.04 v1@11826.25,8628.92 ; v1(11826.25,8632.85) 11838.06,8644.67 C94.1@11838.06,8703.72 ; v1(11893.18,7920.26) U5.95@11944.36,7920.26 ; U5.113@11944.36,8203.72 v1(11995.54,8203.72) C101.1@11995.54,8235.22 ; C101.1@11999.48,8239.15 C93.1@12038.85,8239.15
  Top Layer w15.75: v4(11397.11,6648.6) C132.1@11397.11,6707.66 ; v4(11412.86,6621.04) C132.1@11412.86,6723.41 ; v4(11428.61,6648.6) C132.1@11428.61,6719.47 ; v4(11920.74,8668.29) C133.1@11920.74,8731.28 ; v4(11956.17,8668.29) C133.1@11956.17,8727.34 ; v4(11991.6,8668.29) C133.1@11991.6,8743.09
  Mid-Layer 2 w7.87: TP2.1@9412.86,9711.59 9475.85,9648.6 9475.85,9451.75 9401.05,9376.95 9401.05,8416.32 9444.36,8373.01 9444.36,8058.05 9386.36,8000.06 9386.36,7415.26 9904.99,6896.63 10475.85,6896.63 10771.13,6601.36 11393.18,6601.36 v4(11412.86,6621.04)
  Bottom Layer w7.87: C97.1@11141.21,7849.39 11141.21,7869.07 v1(11160.89,7888.76) 11180.58,7869.07 C92.1@11180.58,7849.39 ; 11389.24,8215.53 R59.1@11434.52,8215.53 ; D1.1@11412.86,8063.96 v1(11412.86,8101.36) ; C98.1@11641.21,7825.77 11641.21,7817.89 v1(11660.89,7798.21) 11680.58,7817.89 C91.1@11680.58,7825.77 ; C99.1@11865.62,7900.57 11873.49,7900.57 v1(11893.18,7920.26) 11873.49,7939.94 C90.1@11865.62,7939.94
  Bottom Layer w15.75: C88.1@11275.07,8002.93 v1(11275.07,8061.99) ; C88.1@11302.63,8002.93 v1(11302.63,8061.99) ; C88.1@11330.19,8006.87 v1(11330.19,8061.99) ; v4(11397.11,6648.6) HDR2.93@11397.12,6711.59 ; v1(11397.11,8656.48) HDR1.93@11397.11,8711.59 ; v4(11428.61,6648.6) HDR2.95@11428.61,6711.59 ; v1(11428.61,8632.85) v1(11428.61,8656.48) HDR1.95@11428.61,8711.59 ; C89.1@11578.22,8278.52 v1(11578.22,8337.58) ; C89.1@11605.78,8278.52 v1(11605.78,8337.58) ; C89.1@11633.33,8282.46 v1(11633.33,8337.58)
  other v1: 11377.43,8215.53
VCC2V5: C2.1 C3.1 C4.1 C5.1 C6.1 C7.1 C8.1 C9.1 C10.1 C11.1 C128.1 C129.1 R64.1 TP7.1 U1.A6 U1.A17 U1.AB6 U1.AB17 U1.F1 U1.F22 U1.U1 U1.U22 U10.2 U10.3 U10.6 U10.7 | length 3137.9
  Top Layer w5: v1(9664.83,7554.11) U1.U1@9684.52,7534.43 ; U1.F1@9684.52,7967.5 v1(9704.2,7987.19) ; v1(9861.68,7317.89) U1.AB6@9881.37,7337.58 ; v1(9861.68,8184.04) U1.A6@9881.37,8164.35 ; U1.AB17@10314.44,7337.58 v1(10334.12,7317.89) ; U1.A17@10314.44,8164.35 v1(10334.12,8184.04) ; U1.U22@10511.29,7534.43 v1(10530.97,7514.74) ; U1.F22@10511.29,7967.5 v1(10530.97,7987.19)
  Top Layer w7.87: v2(10893.18,6467.5) 10944.36,6467.5 11007.35,6530.49 R64.1@11060.5,6530.49
  Top Layer w15.75: C3.1@9404.99,7502.93 9412.86,7506.87 v1(9412.86,7565.92) ; C3.1@9436.48,7502.93 9440.42,7506.87 v1(9440.42,7565.92) ; C3.1@9467.98,7502.93 v1(9467.98,7565.92) ; v1(10441.65,7224.79) 10454.79,7224.79 C2.1@10487.67,7191.91 ; v1(10475,7100) 10475,7132 C2.1@10491.6,7148.6
  Mid-Layer 2 w7.87: v1(9404.99,8148.6) 9428.61,8172.22 9428.61,8365.14 9386.36,8407.38 9386.36,9385.88 9460.11,9459.63 9460.11,9593.48 TP7.1@9412.86,9640.73
  Bottom Layer w15.75: v1(9404.99,8101.36) 9428.61,8077.74 C128.1@9448.3,8077.74 ; C128.1@9428.61,8109.23 9404.99,8132.85 v1(9404.99,8148.6) 9452.23,8101.36 C128.1@9460.11,8101.36 ; C128.1@9432.55,8085.61 9404.99,8113.17 v1(9404.99,8124.98) 9436.48,8093.48 C128.1@9452.23,8093.48 ; v4(10582.15,8132.85) C129.1@10653.02,8132.85 ; v4(10582.15,8172.22) C129.1@10653.02,8172.22
  Bottom Layer w20: v2(10893.18,6467.5) 10914.24,6446.44 U10.6@10991.6,6446.44 ; U10.7@10991.6,6496.44 U10.6@10991.6,6446.44 ; U10.2@11196.33,6496.44 U10.3@11196.33,6446.44 U10.6@10991.6,6446.44
  other v2: 10460.11,6404.51 10538.85,6408.44 10617.59,6408.44 10696.33,6408.44 10775.07,6408.44 10853.81,6408.44 10735.7,6467.5 10814.44,6467.5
